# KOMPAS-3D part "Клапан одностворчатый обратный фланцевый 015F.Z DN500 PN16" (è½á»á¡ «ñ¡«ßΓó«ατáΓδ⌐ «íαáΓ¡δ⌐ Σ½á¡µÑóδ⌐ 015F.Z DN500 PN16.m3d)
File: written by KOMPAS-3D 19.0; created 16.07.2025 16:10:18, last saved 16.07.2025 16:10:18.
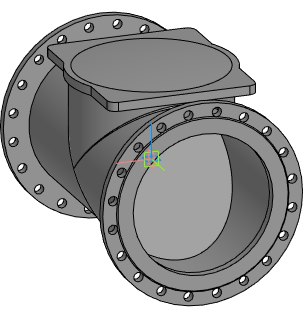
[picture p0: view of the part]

Document properties: Полное имя файла: E:\Dendor Работа Сачек\3D для проектировщиков\5.4 Тип 015F.Z. Клапан одностворчатый обратный фланцевый\stp_Клапан одностворчатый обратный фланцевый 015F.Z PN10_16\Клапан одностворчатый обратный фланцевый 015F.Z DN500 PN16.m3d

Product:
- Part/product: Клапан одностворчатый обратный фланцевый 015F.Z DN500 PN16

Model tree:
1. Операция без истории:1  (labels: Клапан одностворчатый обратный фланцевый 015F.Z DN500 PN16)
2. Операция без истории:2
